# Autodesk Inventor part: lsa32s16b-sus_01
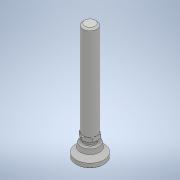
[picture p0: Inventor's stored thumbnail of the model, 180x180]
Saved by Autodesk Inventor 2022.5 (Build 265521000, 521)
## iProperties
Part Number: lsa32s16b-sus_01
Material: 一般
Document SubType Name: Modeling
Designer: ImaoCorp
Density: 1 g/cm^3
Appearance: 既定
Author: ImaoCorp
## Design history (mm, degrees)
feature "lsa32s16b-sus_01"
node "ソリッド1"
